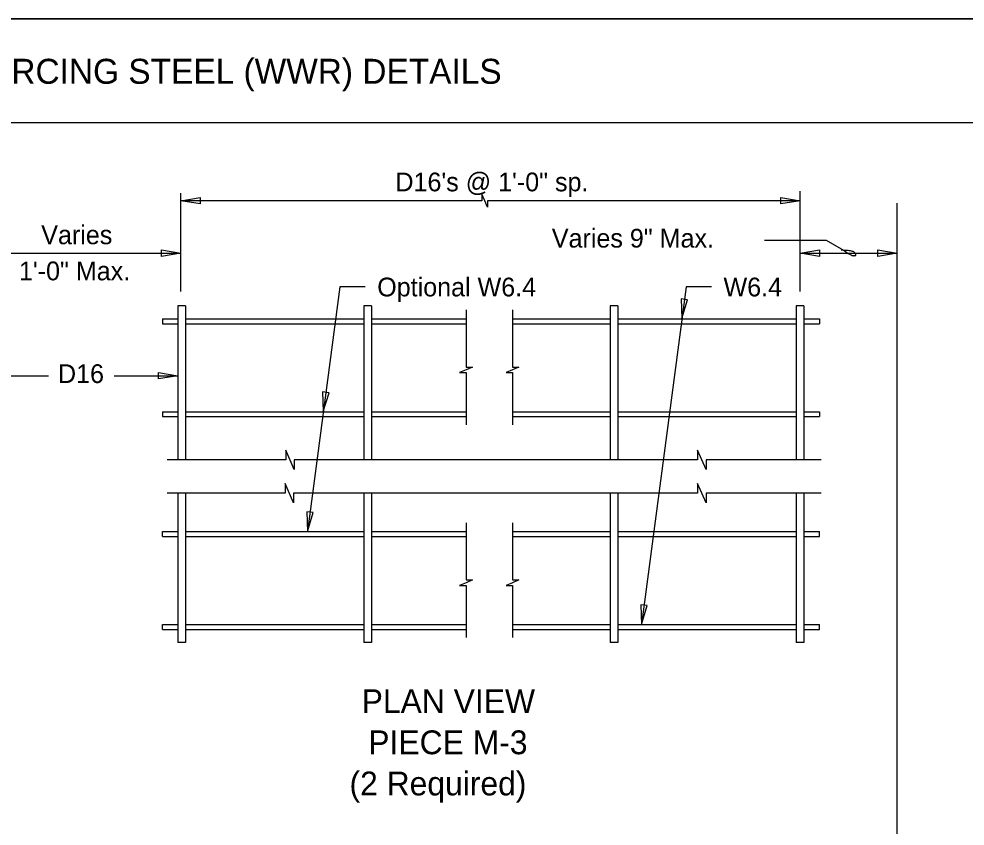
# Model space of a CAD drawing. Extents: x 0 to 20.5, y 0 to 13.
# Drawn here: x 9.79 to 14.87, y 8.63 to 12.97 of the extents above; entities that cross this region are included whole.
import ezdxf

# ---------------------------------------------------------------- set-up
doc = ezdxf.new("R2010")
doc.units = 0
for name, color, linetype in [('ActivePts-ConstElements', 7, 'Continuous'), ('CL_Minor', 7, 'Continuous'), ('Dimension', 7, 'Continuous'), ('Miscellaneous1', 7, 'Continuous'), ('Rebar', 7, 'Continuous'), ('Symbols', 7, 'Continuous'), ('TextStructures', 7, 'Continuous')]:
    doc.layers.add(name, color=color, linetype=linetype)

msp = doc.modelspace()

# ---------------------------------------------------------------- linework, layer by layer
at = {"layer": 'ActivePts-ConstElements'}
msp.add_lwpolyline([(0, 0), (20.5253, 0), (20.5253, 12.9731), (0, 12.9731)], close=True, dxfattribs=at)
at = {"layer": 'CL_Minor'}
msp.add_line((14.5079, 1.1474), (14.5079, 11.9813), dxfattribs=at)
at = {"layer": 'Dimension'}
for p, q in [((-0.008, 12.4165), (20.5253, 12.4165)), ((10.6569, 11.5072), (10.6569, 12.0356)), ((13.9865, 11.5072), (13.9865, 12.0458)), ((9.6569, 11.7132), (10.6569, 11.7132)), ((13.9865, 11.7132), (14.5079, 11.7132)), ((9.6778, 11.0541), (9.9449, 11.0541)), ((10.2984, 11.0541), (10.6413, 11.0541))]:
    msp.add_line(p, q, dxfattribs=at)
for points in [[(13.9865, 11.9954), (12.3061, 11.9954), (12.3061, 11.9609), (12.2911, 11.9954), (12.2761, 12.0298), (12.2761, 11.9954), (10.6569, 11.9954)], [(13.7953, 11.783), (14.1267, 11.783), (14.2202, 11.7289)], [(11.6492, 11.5313), (11.5114, 11.5313), (11.338, 10.2157)], [(13.511, 11.5313), (13.3733, 11.5313), (13.1341, 9.7169)], [(12.1906, 11.408), (12.1906, 11.1007), (12.2251, 11.1007), (12.1906, 11.0857), (12.1562, 11.0707), (12.1906, 11.0707), (12.1906, 10.7907)], [(12.4406, 11.408), (12.4406, 11.1007), (12.475, 11.1007), (12.4406, 11.0857), (12.4061, 11.0707), (12.4406, 11.0707), (12.4406, 10.7907)], [(12.1906, 10.2632), (12.1906, 9.9559), (12.2251, 9.9559), (12.1906, 9.9409), (12.1562, 9.9259), (12.1906, 9.9259), (12.1906, 9.6459)], [(12.4406, 10.2632), (12.4406, 9.9559), (12.475, 9.9559), (12.4406, 9.9409), (12.4061, 9.9259), (12.4406, 9.9259), (12.4406, 9.6459)]]:
    msp.add_lwpolyline(points, dxfattribs=at)
for points in [[(10.761, 11.9777), (10.6569, 11.9954), (10.761, 12.013)], [(10.761, 11.9777), (10.6569, 11.9954), (10.761, 12.013)], [(13.8824, 12.013), (13.9865, 11.9954), (13.8824, 11.9777)], [(10.5528, 11.7308), (10.6569, 11.7132), (10.5528, 11.6955)], [(14.0907, 11.6955), (13.9865, 11.7132), (14.0907, 11.7308)], [(14.4038, 11.7308), (14.5079, 11.7132), (14.4038, 11.6955)], [(13.3469, 11.4672), (13.3508, 11.3617), (13.3819, 11.4626)], [(10.5372, 11.0717), (10.6413, 11.0541), (10.5372, 11.0364)], [(11.4193, 10.9672), (11.4232, 10.8617), (11.4542, 10.9626)], [(11.3344, 10.3224), (11.3383, 10.2169), (11.3694, 10.3178)], [(13.1302, 9.8224), (13.1341, 9.7169), (13.1652, 9.8178)]]:
    msp.add_lwpolyline(points, close=True, dxfattribs=at)
msp.add_open_spline([(14.2202, 11.7289), (14.2589, 11.6997), (14.2872, 11.6997), (14.2872, 11.7059), (14.2687, 11.7286), (14.2079, 11.7286)], degree=2, dxfattribs=at)
at = {"layer": 'Miscellaneous1'}
msp.add_lwpolyline([(0, 12.9731), (20.5253, 12.9731), (20.5253, 0), (0, 0)], close=True, dxfattribs=at)
at = {"layer": 'Rebar'}
for p, q in [((10.683, 11.4305), (10.6413, 11.4305)), ((10.6413, 11.4305), (10.6413, 10.6014)), ((10.683, 11.4305), (10.683, 10.6014)), ((11.683, 11.4305), (11.6413, 11.4305)), ((11.6413, 11.4305), (11.6413, 10.6014)), ((11.683, 11.4305), (11.683, 10.6014)), ((13.0074, 11.4305), (12.9657, 11.4305)), ((12.9657, 11.4305), (12.9657, 10.6014)), ((13.0074, 11.4305), (13.0074, 10.6014)), ((14.0074, 11.4305), (13.9657, 11.4305)), ((13.9657, 11.4305), (13.9657, 10.6014)), ((14.0074, 11.4305), (14.0074, 10.6014)), ((10.558, 11.3605), (10.6413, 11.3605)), ((10.558, 11.3605), (10.558, 11.3339)), ((10.683, 11.3605), (11.6413, 11.3605)), ((11.683, 11.3605), (12.1906, 11.3605)), ((12.4406, 11.3605), (12.9657, 11.3605)), ((13.0074, 11.3605), (13.9657, 11.3605)), ((14.0074, 11.3605), (14.0907, 11.3605)), ((14.0907, 11.3605), (14.0907, 11.3339)), ((10.558, 11.3339), (10.6413, 11.3339)), ((10.683, 11.3339), (11.6413, 11.3339)), ((11.683, 11.3339), (12.1906, 11.3339)), ((12.4406, 11.3339), (12.9657, 11.3339)), ((13.0074, 11.3339), (13.9657, 11.3339)), ((14.0074, 11.3339), (14.0907, 11.3339)), ((10.558, 10.8605), (10.6413, 10.8605)), ((10.558, 10.8605), (10.558, 10.8339)), ((10.683, 10.8605), (11.6413, 10.8605)), ((11.683, 10.8605), (12.1906, 10.8605)), ((12.4406, 10.8605), (12.9657, 10.8605)), ((13.0074, 10.8605), (13.9657, 10.8605)), ((14.0074, 10.8605), (14.0907, 10.8605)), ((14.0907, 10.8605), (14.0907, 10.8339)), ((10.558, 10.8339), (10.6413, 10.8339)), ((10.683, 10.8339), (11.6413, 10.8339)), ((11.683, 10.8339), (12.1906, 10.8339)), ((12.4406, 10.8339), (12.9657, 10.8339)), ((13.0074, 10.8339), (13.9657, 10.8339)), ((14.0074, 10.8339), (14.0907, 10.8339)), ((10.6413, 10.4224), (10.6413, 9.6191)), ((10.683, 10.4224), (10.683, 9.6191)), ((11.6413, 10.4224), (11.6413, 9.6191)), ((11.683, 10.4224), (11.683, 9.6191)), ((12.9657, 10.4224), (12.9657, 9.6191)), ((13.0074, 10.4224), (13.0074, 9.6191)), ((13.9657, 10.4224), (13.9657, 9.6191)), ((14.0074, 10.4224), (14.0074, 9.6191)), ((10.558, 10.2157), (10.6413, 10.2157)), ((10.558, 10.1891), (10.558, 10.2157)), ((10.558, 10.1891), (10.6413, 10.1891)), ((10.683, 10.2157), (11.6413, 10.2157)), ((10.683, 10.1891), (11.6413, 10.1891)), ((11.683, 10.2157), (12.1906, 10.2157)), ((11.683, 10.1891), (12.1906, 10.1891)), ((12.4406, 10.2157), (12.9657, 10.2157)), ((12.4406, 10.1891), (12.9657, 10.1891)), ((13.0074, 10.2157), (13.9657, 10.2157)), ((13.0074, 10.1891), (13.9657, 10.1891)), ((14.0074, 10.2157), (14.0907, 10.2157)), ((14.0074, 10.1891), (14.0907, 10.1891)), ((14.0907, 10.1891), (14.0907, 10.2157)), ((10.558, 9.7157), (10.6413, 9.7157)), ((10.558, 9.6891), (10.558, 9.7157)), ((10.558, 9.6891), (10.6413, 9.6891)), ((10.683, 9.7157), (11.6413, 9.7157)), ((10.683, 9.6891), (11.6413, 9.6891)), ((11.683, 9.7157), (12.1906, 9.7157)), ((11.683, 9.6891), (12.1906, 9.6891)), ((12.4406, 9.7157), (12.9657, 9.7157)), ((12.4406, 9.6891), (12.9657, 9.6891)), ((13.0074, 9.7157), (13.9657, 9.7157)), ((13.0074, 9.6891), (13.9657, 9.6891)), ((14.0074, 9.7157), (14.0907, 9.7157)), ((14.0074, 9.6891), (14.0907, 9.6891)), ((14.0907, 9.6891), (14.0907, 9.7157)), ((10.683, 9.6191), (10.6413, 9.6191)), ((11.683, 9.6191), (11.6413, 9.6191)), ((13.0074, 9.6191), (12.9657, 9.6191)), ((14.0074, 9.6191), (13.9657, 9.6191))]:
    msp.add_line(p, q, dxfattribs=at)
at = {"layer": 'Symbols'}
for points in [[(12.3945, 10.6014), (11.266, 10.6014), (11.266, 10.5498), (11.221, 10.6531), (11.221, 10.6014), (10.5846, 10.6014)], [(14.1004, 10.6014), (13.4809, 10.6014), (13.4809, 10.5498), (13.4359, 10.6531), (13.4359, 10.6014), (12.3945, 10.6014)], [(12.3945, 10.4224), (11.2637, 10.4224), (11.2637, 10.3707), (11.2187, 10.4741), (11.2187, 10.4224), (10.5846, 10.4224)], [(14.1004, 10.4224), (13.4809, 10.4224), (13.4809, 10.3707), (13.4359, 10.4741), (13.4359, 10.4224), (12.3945, 10.4224)]]:
    msp.add_lwpolyline(points, dxfattribs=at)

# ---------------------------------------------------------------- texts
at = {"layer": 'Dimension'}
for s, p in [('D16\'s @ 1\'-0" sp.', (11.811, 12.0458)), ('Varies', (9.9068, 11.7613)), ('Varies 9" Max.', (12.6519, 11.7433)), ('1\'-0" Max.', (9.787, 11.5672)), ('Optional W6.4', (11.7132, 11.4807)), ('W6.4', (13.575, 11.4807)), ('D16', (9.9969, 11.0147))]:
    msp.add_text(s, height=0.1008, dxfattribs=at).set_placement(p)
at = {"layer": 'TextStructures'}
for s, height, p in [('ALTERNATE REINFORCING STEEL (WWR) DETAILS', 0.1344, (7.9585, 12.6241)), ('PLAN VIEW', 0.128, (11.6295, 9.2396)), ('PIECE M-3', 0.128, (11.6652, 9.0183)), ('(2 Required)', 0.128, (11.564, 8.7969))]:
    msp.add_text(s, height=height, dxfattribs=at).set_placement(p)

doc.saveas('drawing.dxf')
